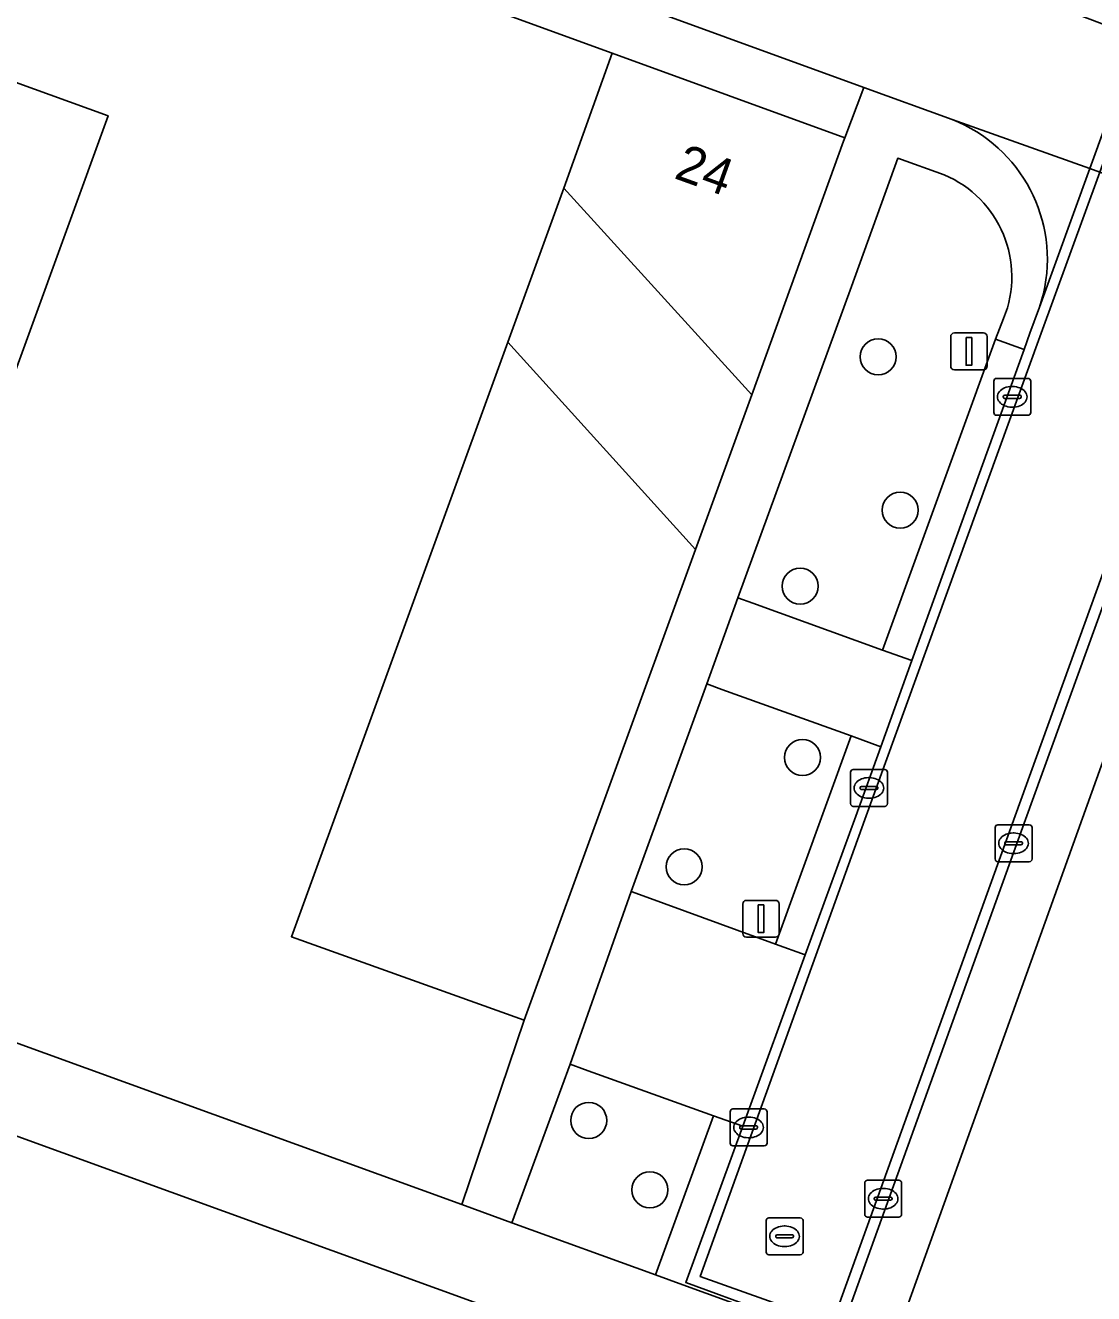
# Model space of a CAD drawing. Extents: x 155275 to 156265, y 382654 to 383635.
# Drawn here: x 155842.67 to 155871.63, y 382876.67 to 382911.07 of the extents above; entities that cross this region are included whole.
import ezdxf

# ---------------------------------------------------------------- set-up
doc = ezdxf.new("R2010")
doc.units = 0
for name, color, linetype in [('IMGEO_Boom', 7, 'Continuous'), ('IMGEO_Erf', 7, 'Continuous'), ('IMGEO_Groenvoorziening', 7, 'Continuous'), ('IMGEO_Kolk', 7, 'Continuous'), ('IMGEO_Lichtmast', 7, 'Continuous'), ('IMGEO_Loofbos', 7, 'Continuous'), ('IMGEO_Pand', 7, 'Continuous'), ('IMGEO_Pand_nummerreeks', 7, 'Continuous'), ('IMGEO_Pand_overbouw', 7, 'Continuous'), ('IMGEO_Parkeervlak_open', 7, 'Continuous'), ('IMGEO_Rijbaan_lokaal_gesloten', 7, 'Continuous'), ('IMGEO_Rijbaan_lokaal_open', 7, 'Continuous'), ('IMGEO_Rioolput', 7, 'Continuous'), ('IMGEO_Voetpad_open', 7, 'Continuous')]:
    doc.layers.add(name, color=color, linetype=linetype)

msp = doc.modelspace()

# ---------------------------------------------------------------- linework, layer by layer
at = {"layer": 'IMGEO_Boom'}
for centre in [(155865.791, 382902.083), (155866.386, 382897.922), (155863.674, 382895.863), (155863.737, 382891.215), (155860.529, 382888.251), (155857.941, 382881.373), (155859.601, 382879.488)]:
    msp.add_circle(centre, 0.489, dxfattribs=at)
at = {"layer": 'IMGEO_Erf'}
for points in [[(155858.578, 382910.318), (155778.11, 382939.582), (155776.003, 382933.692), (155781.968, 382931.558), (155779.643, 382925.014), (155784.554, 382923.227), (155784.283, 382922.477), (155785.216, 382922.133), (155781.233, 382911.153), (155780.932, 382911.263), (155781.358, 382912.438), (155777.396, 382913.993), (155776.968, 382912.818), (155770.335, 382915.238), (155770.972, 382916.985), (155770.033, 382917.328), (155767.593, 382910.639), (155854.498, 382879.089), (155856.191, 382884.092), (155849.881, 382886.353), (155855.747, 382902.481), (155860.835, 382896.859), (155862.363, 382901.052), (155857.263, 382906.66)], [(155841.333, 382909.913), (155844.906, 382908.621), (155838.303, 382890.458), (155837.965, 382890.581), (155838.054, 382890.826), (155832.144, 382892.932), (155832.055, 382892.682), (155831.735, 382892.796), (155831.824, 382893.046), (155831.334, 382893.22), (155831.245, 382892.971), (155827.969, 382894.144), (155831.064, 382902.797), (155834.857, 382901.44), (155835.722, 382903.86), (155838.749, 382902.766)]]:
    msp.add_lwpolyline(points, close=True, dxfattribs=at)
msp.add_lwpolyline([(155875.141, 382900.359), (155872.725, 382893.446), (155866.062, 382874.889), (155953.058, 382843.257), (155959.029, 382859.144), (155962.877, 382868.971)], dxfattribs=at)
at = {"layer": 'IMGEO_Groenvoorziening'}
for points in [[(155867.576, 382907.023), (155866.322, 382907.469), (155865.065, 382903.995), (155861.981, 382895.545), (155862.389, 382895.398), (155865.907, 382894.131), (155868.975, 382902.566)], [(155868.975, 382902.566), (155869.192, 382903.122)]]:
    msp.add_lwpolyline(points, dxfattribs=at)
for points in [[(155865.057, 382891.799), (155861.548, 382893.064), (155861.14, 382893.211), (155859.094, 382887.583), (155859.513, 382887.43), (155863.002, 382886.155)], [(155861.325, 382881.496), (155857.831, 382882.752), (155857.436, 382882.894), (155855.852, 382878.598), (155859.753, 382877.182)]]:
    msp.add_lwpolyline(points, close=True, dxfattribs=at)
msp.add_arc((155866.41, 382904.255), 3.004, 337.8507, 67.1531, dxfattribs=at)
at = {"layer": 'IMGEO_Kolk'}
for p, q in [((155868.925, 382900.572), (155868.925, 382901.424)), ((155869, 382901.498), (155869.852, 382901.498)), ((155869.926, 382901.424), (155869.926, 382900.572)), ((155869.184, 382900.992), (155869.184, 382901.004)), ((155869.622, 382900.955), (155869.224, 382900.955)), ((155869.227, 382901.041), (155869.625, 382901.041)), ((155869.413, 382901.278), (155869.438, 382901.278)), ((155869.668, 382901.004), (155869.668, 382900.992)), ((155869.436, 382900.718), (155869.411, 382900.718)), ((155869.852, 382900.498), (155869, 382900.498)), ((155865.04, 382889.964), (155865.04, 382890.816)), ((155865.115, 382890.89), (155865.967, 382890.89)), ((155865.528, 382890.67), (155865.553, 382890.67)), ((155866.041, 382890.816), (155866.041, 382889.964)), ((155865.299, 382890.384), (155865.299, 382890.396)), ((155865.737, 382890.347), (155865.339, 382890.347)), ((155865.342, 382890.433), (155865.74, 382890.433)), ((155865.783, 382890.396), (155865.783, 382890.384)), ((155865.551, 382890.11), (155865.526, 382890.11)), ((155865.967, 382889.89), (155865.115, 382889.89)), ((155868.962, 382888.463), (155868.962, 382889.315)), ((155869.037, 382889.389), (155869.889, 382889.389)), ((155869.963, 382889.315), (155869.963, 382888.463)), ((155869.264, 382888.932), (155869.662, 382888.932)), ((155869.45, 382889.169), (155869.475, 382889.169)), ((155869.221, 382888.883), (155869.221, 382888.895)), ((155869.659, 382888.846), (155869.261, 382888.846)), ((155869.473, 382888.609), (155869.448, 382888.609)), ((155869.705, 382888.895), (155869.705, 382888.883)), ((155869.889, 382888.389), (155869.037, 382888.389)), ((155861.851, 382881.682), (155862.703, 382881.682)), ((155861.776, 382880.756), (155861.776, 382881.608)), ((155862.264, 382881.462), (155862.289, 382881.462)), ((155862.777, 382881.608), (155862.777, 382880.756)), ((155862.035, 382881.176), (155862.035, 382881.188)), ((155862.473, 382881.139), (155862.075, 382881.139)), ((155862.078, 382881.225), (155862.476, 382881.225)), ((155862.519, 382881.188), (155862.519, 382881.176)), ((155862.703, 382880.682), (155861.851, 382880.682)), ((155862.287, 382880.902), (155862.262, 382880.902)), ((155865.424, 382878.823), (155865.424, 382879.675)), ((155865.499, 382879.749), (155866.351, 382879.749)), ((155866.425, 382879.675), (155866.425, 382878.823)), ((155865.726, 382879.292), (155866.124, 382879.292)), ((155865.912, 382879.529), (155865.937, 382879.529)), ((155865.683, 382879.243), (155865.683, 382879.255)), ((155866.121, 382879.206), (155865.723, 382879.206)), ((155865.935, 382878.969), (155865.91, 382878.969)), ((155866.167, 382879.255), (155866.167, 382879.243)), ((155866.351, 382878.749), (155865.499, 382878.749))]:
    msp.add_line(p, q, dxfattribs=at)
for points in [[(155868.925, 382900.572), (155868.925, 382901.424)], [(155869, 382901.498), (155869.852, 382901.498)], [(155869.926, 382901.424), (155869.926, 382900.572)], [(155869.852, 382900.498), (155869, 382900.498)], [(155865.04, 382889.964), (155865.04, 382890.816)], [(155865.115, 382890.89), (155865.967, 382890.89)], [(155866.041, 382890.816), (155866.041, 382889.964)], [(155865.967, 382889.89), (155865.115, 382889.89)], [(155868.962, 382888.463), (155868.962, 382889.315)], [(155869.037, 382889.389), (155869.889, 382889.389)], [(155869.963, 382889.315), (155869.963, 382888.463)], [(155869.889, 382888.389), (155869.037, 382888.389)], [(155861.851, 382881.682), (155862.703, 382881.682)], [(155861.776, 382880.756), (155861.776, 382881.608)], [(155862.777, 382881.608), (155862.777, 382880.756)], [(155862.703, 382880.682), (155861.851, 382880.682)], [(155865.424, 382878.823), (155865.424, 382879.675)], [(155865.499, 382879.749), (155866.351, 382879.749)], [(155866.425, 382879.675), (155866.425, 382878.823)], [(155866.351, 382878.749), (155865.499, 382878.749)]]:
    msp.add_lwpolyline(points, dxfattribs=at)
for centre, radius, start, end in [((155869.002, 382901.422), 0.0765, 91.552, 178.448), ((155869.002, 382901.422), 0.0765, 91.552, 178.448), ((155869.85, 382901.422), 0.0765, 1.552, 88.448), ((155869.85, 382901.422), 0.0765, 1.552, 88.448), ((155869.224, 382901.001), 0.0403, 85.8775, 175.7526), ((155869.221, 382900.991), 0.0366, 178.938, 274.7102), ((155869.625, 382900.998), 0.043, 264.8664, 352.4533), ((155869.629, 382901.003), 0.0386, 1.7309, 96.639), ((155869.002, 382900.574), 0.0765, 181.552, 268.448), ((155869.002, 382900.574), 0.0765, 181.552, 268.448), ((155869.85, 382900.574), 0.0765, 271.552, 358.448), ((155869.85, 382900.574), 0.0765, 271.552, 358.448), ((155865.117, 382890.814), 0.0765, 91.552, 178.448), ((155865.117, 382890.814), 0.0765, 91.552, 178.448), ((155865.965, 382890.814), 0.0765, 1.552, 88.448), ((155865.965, 382890.814), 0.0765, 1.552, 88.448), ((155865.339, 382890.393), 0.0403, 85.8775, 175.7526), ((155865.336, 382890.383), 0.0366, 178.938, 274.7102), ((155865.74, 382890.39), 0.043, 264.8664, 352.4533), ((155865.744, 382890.395), 0.0386, 1.7309, 96.639), ((155865.117, 382889.966), 0.0765, 181.552, 268.448), ((155865.117, 382889.966), 0.0765, 181.552, 268.448), ((155865.965, 382889.966), 0.0765, 271.552, 358.448), ((155865.965, 382889.966), 0.0765, 271.552, 358.448), ((155869.039, 382889.313), 0.0765, 91.552, 178.448), ((155869.039, 382889.313), 0.0765, 91.552, 178.448), ((155869.887, 382889.313), 0.0765, 1.552, 88.448), ((155869.887, 382889.313), 0.0765, 1.552, 88.448), ((155869.261, 382888.892), 0.0403, 85.8775, 175.7526), ((155869.666, 382888.894), 0.0386, 1.7309, 96.639), ((155869.258, 382888.882), 0.0366, 178.938, 274.7102), ((155869.662, 382888.889), 0.043, 264.8664, 352.4533), ((155869.039, 382888.465), 0.0765, 181.552, 268.448), ((155869.039, 382888.465), 0.0765, 181.552, 268.448), ((155869.887, 382888.465), 0.0765, 271.552, 358.448), ((155869.887, 382888.465), 0.0765, 271.552, 358.448), ((155861.853, 382881.606), 0.0765, 91.552, 178.448), ((155861.853, 382881.606), 0.0765, 91.552, 178.448), ((155862.701, 382881.606), 0.0765, 1.552, 88.448), ((155862.701, 382881.606), 0.0765, 1.552, 88.448), ((155862.075, 382881.185), 0.0403, 85.8775, 175.7526), ((155862.072, 382881.175), 0.0366, 178.938, 274.7102), ((155862.476, 382881.182), 0.043, 264.8664, 352.4533), ((155862.48, 382881.187), 0.0386, 1.7309, 96.639), ((155861.853, 382880.758), 0.0765, 181.552, 268.448), ((155861.853, 382880.758), 0.0765, 181.552, 268.448), ((155862.701, 382880.758), 0.0765, 271.552, 358.448), ((155862.701, 382880.758), 0.0765, 271.552, 358.448), ((155865.501, 382879.673), 0.0765, 91.552, 178.448), ((155865.501, 382879.673), 0.0765, 91.552, 178.448), ((155866.349, 382879.673), 0.0765, 1.552, 88.448), ((155866.349, 382879.673), 0.0765, 1.552, 88.448), ((155865.723, 382879.252), 0.0403, 85.8775, 175.7526), ((155866.128, 382879.254), 0.0386, 1.7309, 96.639), ((155865.72, 382879.242), 0.0366, 178.938, 274.7102), ((155866.124, 382879.249), 0.043, 264.8664, 352.4533), ((155865.501, 382878.825), 0.0765, 181.552, 268.448), ((155865.501, 382878.825), 0.0765, 181.552, 268.448), ((155866.349, 382878.825), 0.0765, 271.552, 358.448), ((155866.349, 382878.825), 0.0765, 271.552, 358.448)]:
    msp.add_arc(centre, radius, start, end, dxfattribs=at)
for centre, major_axis, ratio, start_param, end_param in [((155869.412, 382900.998), (-0.387, 0.002), 0.722429, 4.712389, 7.853982), ((155869.437, 382900.998), (-0.39, 0.002), 0.717154, 1.570796, 4.712389), ((155865.527, 382890.39), (-0.387, 0.002), 0.722429, 4.712389, 7.853982), ((155865.552, 382890.39), (-0.39, 0.002), 0.717154, 1.570796, 4.712389), ((155869.449, 382888.889), (-0.387, 0.002), 0.722429, 4.712389, 7.853982), ((155869.474, 382888.889), (-0.39, 0.002), 0.717154, 1.570796, 4.712389), ((155862.263, 382881.182), (-0.387, 0.002), 0.722429, 4.712389, 7.853982), ((155862.288, 382881.182), (-0.39, 0.002), 0.717154, 1.570796, 4.712389), ((155865.911, 382879.249), (-0.387, 0.002), 0.722429, 4.712389, 7.853982), ((155865.936, 382879.249), (-0.39, 0.002), 0.717154, 1.570796, 4.712389)]:
    msp.add_ellipse(centre, major_axis=major_axis, ratio=ratio, start_param=start_param, end_param=end_param, dxfattribs=at)
at = {"layer": 'IMGEO_Lichtmast'}
for p, q in [((155867.856, 382902.731), (155868.646, 382902.731)), ((155868.646, 382902.731), (155867.856, 382902.731)), ((155867.756, 382901.831), (155867.756, 382902.631)), ((155867.756, 382902.631), (155867.756, 382901.831)), ((155868.746, 382902.631), (155868.746, 382901.831)), ((155868.746, 382901.831), (155868.746, 382902.631)), ((155868.646, 382901.731), (155867.856, 382901.731)), ((155867.856, 382901.731), (155868.646, 382901.731)), ((155862.117, 382886.441), (155862.117, 382887.241)), ((155862.117, 382887.241), (155862.117, 382886.441)), ((155862.217, 382887.341), (155863.007, 382887.341)), ((155863.007, 382887.341), (155862.217, 382887.341)), ((155863.107, 382887.241), (155863.107, 382886.441)), ((155863.107, 382886.441), (155863.107, 382887.241)), ((155863.007, 382886.341), (155862.217, 382886.341)), ((155862.217, 382886.341), (155863.007, 382886.341))]:
    msp.add_line(p, q, dxfattribs=at)
for points in [[(155868.176, 382902.606), (155868.326, 382902.606), (155868.326, 382901.856), (155868.176, 382901.856), (155868.176, 382902.606)], [(155862.537, 382887.216), (155862.687, 382887.216), (155862.687, 382886.466), (155862.537, 382886.466), (155862.537, 382887.216)]]:
    msp.add_lwpolyline(points, dxfattribs=at)
for centre, start, end in [((155867.856, 382902.631), 90, 180), ((155867.856, 382902.631), 90, 180), ((155868.646, 382902.631), 0, 90), ((155868.646, 382902.631), 360, 90), ((155867.856, 382901.831), 180, 270), ((155867.856, 382901.831), 180, 270), ((155868.646, 382901.831), 270, 0), ((155868.646, 382901.831), 270, 0), ((155862.217, 382887.241), 90, 180), ((155862.217, 382887.241), 90, 180), ((155863.007, 382887.241), 0, 90), ((155863.007, 382887.241), 360, 90), ((155862.217, 382886.441), 180, 270), ((155862.217, 382886.441), 180, 270), ((155863.007, 382886.441), 270, 0), ((155863.007, 382886.441), 270, 0)]:
    msp.add_arc(centre, 0.1, start, end, dxfattribs=at)
at = {"layer": 'IMGEO_Loofbos'}
msp.add_lwpolyline([(155962.277, 382837.428), (155865.28, 382872.649), (155863.949, 382873.132), (155772.846, 382906.212), (155660.759, 382947.032), (155649.875, 382951.072)], dxfattribs=at)
at = {"layer": 'IMGEO_Pand'}
for points in [[(155864.853, 382907.928), (155864.887, 382908.023), (155858.578, 382910.318), (155857.263, 382906.66), (155862.363, 382901.052)], [(155844.906, 382908.621), (155841.333, 382909.913), (155838.749, 382902.766), (155835.722, 382903.86), (155834.857, 382901.44), (155831.064, 382902.797), (155827.969, 382894.144), (155831.245, 382892.971), (155831.334, 382893.22), (155831.824, 382893.046), (155831.735, 382892.796), (155832.055, 382892.682), (155832.144, 382892.932), (155838.054, 382890.826), (155837.965, 382890.581), (155838.303, 382890.458)], [(155860.835, 382896.859), (155855.747, 382902.481), (155849.881, 382886.353), (155856.191, 382884.092)]]:
    msp.add_lwpolyline(points, close=True, dxfattribs=at)
at = {"layer": 'IMGEO_Pand_overbouw'}
msp.add_lwpolyline([(155862.363, 382901.052), (155857.263, 382906.66), (155855.747, 382902.481), (155860.835, 382896.859)], close=True, dxfattribs=at)
at = {"layer": 'IMGEO_Parkeervlak_open'}
for points in [[(155866.703, 382893.844), (155865.907, 382894.131), (155862.389, 382895.398), (155861.981, 382895.545), (155861.14, 382893.211), (155861.548, 382893.064), (155865.057, 382891.799), (155865.861, 382891.509)], [(155863.81, 382885.859), (155863.002, 382886.155), (155859.513, 382887.43), (155859.094, 382887.583), (155857.436, 382882.894), (155857.831, 382882.752), (155861.325, 382881.496), (155862.116, 382881.212)]]:
    msp.add_lwpolyline(points, close=True, dxfattribs=at)
at = {"layer": 'IMGEO_Rijbaan_lokaal_gesloten'}
for points in [[(155873.092, 382910.654), (155872.823, 382910.756), (155871.528, 382907.192), (155871.798, 382907.096)], [(155875.66, 382905.722), (155875.38, 382905.822), (155873.745, 382901.362), (155869.503, 382889.63), (155864.547, 382875.86), (155860.964, 382877.138), (155865.427, 382889.535), (155870.173, 382902.627), (155871.798, 382907.096), (155871.528, 382907.192), (155870.162, 382903.434), (155869.905, 382902.728), (155869.745, 382902.284), (155866.703, 382893.844), (155865.861, 382891.509), (155865.183, 382889.627), (155863.81, 382885.859), (155862.116, 382881.212), (155860.573, 382876.977), (155864.713, 382875.461), (155869.782, 382889.53), (155874.032, 382901.26), (155874.382, 382902.22)]]:
    msp.add_lwpolyline(points, close=True, dxfattribs=at)
at = {"layer": 'IMGEO_Rijbaan_lokaal_open'}
for points in [[(155779.611, 382944.594), (155777.389, 382945.399), (155777.321, 382945.404), (155773.631, 382946.766), (155772.36, 382943.272), (155776.11, 382941.886), (155776.209, 382941.85), (155778.386, 382941.058), (155778.616, 382940.974), (155865.403, 382909.39), (155867.798, 382908.519), (155871.528, 382907.192), (155872.823, 382910.756), (155869.136, 382912.156), (155866.718, 382913.032)], [(155875.38, 382905.822), (155871.798, 382907.096), (155870.173, 382902.627), (155865.427, 382889.535), (155860.964, 382877.138), (155864.547, 382875.86), (155869.503, 382889.63), (155873.745, 382901.362)]]:
    msp.add_lwpolyline(points, close=True, dxfattribs=at)
for points in [[(155871.528, 382907.192), (155867.798, 382908.519)], [(155870.269, 382903.799), (155870.162, 382903.434), (155871.528, 382907.192)]]:
    msp.add_lwpolyline(points, dxfattribs=at)
msp.add_arc((155866.303, 382904.73), 4.074, 346.7944, 68.4713, dxfattribs=at)
at = {"layer": 'IMGEO_Rioolput'}
for p, q in [((155862.752, 382877.803), (155862.752, 382878.655)), ((155862.827, 382878.729), (155863.679, 382878.729)), ((155863.753, 382878.655), (155863.753, 382877.803)), ((155863.054, 382878.272), (155863.452, 382878.272)), ((155863.24, 382878.509), (155863.265, 382878.509)), ((155863.011, 382878.223), (155863.011, 382878.235)), ((155863.449, 382878.186), (155863.051, 382878.186)), ((155863.263, 382877.949), (155863.238, 382877.949)), ((155863.495, 382878.235), (155863.495, 382878.223)), ((155863.679, 382877.729), (155862.827, 382877.729))]:
    msp.add_line(p, q, dxfattribs=at)
for points in [[(155862.752, 382877.803), (155862.752, 382878.655)], [(155862.827, 382878.729), (155863.679, 382878.729)], [(155863.753, 382878.655), (155863.753, 382877.803)], [(155863.679, 382877.729), (155862.827, 382877.729)]]:
    msp.add_lwpolyline(points, dxfattribs=at)
for centre, radius, start, end in [((155862.829, 382878.653), 0.0765, 91.552, 178.448), ((155862.829, 382878.653), 0.0765, 91.552, 178.448), ((155863.677, 382878.653), 0.0765, 1.552, 88.448), ((155863.677, 382878.653), 0.0765, 1.552, 88.448), ((155863.051, 382878.232), 0.0403, 85.8775, 175.7526), ((155863.456, 382878.234), 0.0386, 1.7309, 96.639), ((155863.048, 382878.222), 0.0366, 178.938, 274.7102), ((155863.452, 382878.229), 0.043, 264.8664, 352.4533), ((155862.829, 382877.805), 0.0765, 181.552, 268.448), ((155862.829, 382877.805), 0.0765, 181.552, 268.448), ((155863.677, 382877.805), 0.0765, 271.552, 358.448), ((155863.677, 382877.805), 0.0765, 271.552, 358.448)]:
    msp.add_arc(centre, radius, start, end, dxfattribs=at)
for centre, major_axis, ratio, start_param, end_param in [((155863.239, 382878.229), (-0.387, 0.002), 0.722429, 4.712389, 7.853982), ((155863.264, 382878.229), (-0.39, 0.002), 0.717154, 1.570796, 4.712389)]:
    msp.add_ellipse(centre, major_axis=major_axis, ratio=ratio, start_param=start_param, end_param=end_param, dxfattribs=at)
at = {"layer": 'IMGEO_Voetpad_open'}
for points in [[(155687.76, 382939.71), (155661.6, 382949.239), (155660.759, 382947.032), (155772.846, 382906.212), (155863.949, 382873.132), (155864.759, 382875.363), (155860.495, 382876.912), (155859.753, 382877.182), (155855.852, 382878.598), (155854.498, 382879.089), (155767.593, 382910.639), (155765.941, 382911.239), (155762.029, 382912.659), (155761.338, 382912.91), (155757.172, 382914.424), (155755.688, 382914.965)], [(155778.616, 382940.974), (155778.11, 382939.582), (155858.578, 382910.318), (155864.887, 382908.023), (155865.403, 382909.39)], [(155869.745, 382902.284), (155868.975, 382902.566), (155865.907, 382894.131), (155866.703, 382893.844)], [(155865.861, 382891.509), (155865.057, 382891.799), (155863.002, 382886.155), (155863.81, 382885.859), (155865.183, 382889.627)]]:
    msp.add_lwpolyline(points, close=True, dxfattribs=at)
for points in [[(155867.798, 382908.519), (155865.403, 382909.39), (155864.887, 382908.023), (155864.853, 382907.928), (155862.363, 382901.052), (155860.835, 382896.859), (155856.191, 382884.092), (155854.498, 382879.089), (155855.852, 382878.598), (155857.436, 382882.894), (155859.094, 382887.583)], [(155859.094, 382887.583), (155861.14, 382893.211), (155861.981, 382895.545), (155865.065, 382903.995), (155866.322, 382907.469), (155867.576, 382907.023)], [(155869.192, 382903.122), (155868.975, 382902.566), (155869.745, 382902.284), (155869.905, 382902.728), (155870.162, 382903.434), (155870.269, 382903.799)], [(155874.382, 382902.22), (155874.032, 382901.26), (155869.782, 382889.53), (155864.713, 382875.461), (155860.573, 382876.977), (155862.116, 382881.212)], [(155862.116, 382881.212), (155861.325, 382881.496), (155859.753, 382877.182), (155860.495, 382876.912), (155864.759, 382875.363), (155866.062, 382874.889), (155872.725, 382893.446), (155875.141, 382900.359)]]:
    msp.add_lwpolyline(points, dxfattribs=at)
for centre, radius, start, end in [((155866.303, 382904.73), 4.074, 346.7944, 68.4713), ((155866.41, 382904.255), 3.004, 337.8507, 67.1531)]:
    msp.add_arc(centre, radius, start, end, dxfattribs=at)

# ---------------------------------------------------------------- texts
at = {"layer": 'IMGEO_Pand_nummerreeks'}
msp.add_text('24', height=1, rotation=340.21, dxfattribs=at).set_placement((155860.225, 382906.937))

doc.saveas('drawing.dxf')
